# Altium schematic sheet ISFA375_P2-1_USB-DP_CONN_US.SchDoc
size 431 x 279 mm; Date: Not shown in title block; ApprovedBy: Not shown in title block; CheckedBy: Not shown in title block; Author: Not shown in title block; CompanyName: Not shown in title block; DrawnBy: Thomas Mauer; Engineer: Not shown in title block; Organization: Not shown in title block; Address1: Not shown in title block; Address2: Not shown in title block; Address3: Not shown in title block; Address4: Not shown in title block; DocumentNumber: 11; Revision: Use project parameter SCH_Rev; SheetNumber: 11; SheetTotal: 11; PageSetup: Record=PageOptions¦CenterHorizontal=True¦CenterVertical=True¦PrintScale=1.00¦XCorrection=1.00¦YCorrection=1.00¦PrintKind=0¦BorderSize=5000000¦LeftOffset=0¦BottomOffset=0¦Orientation=2¦PaperLength=1000¦PaperWidth=1000¦Scale=100¦PaperSource=15¦PrintQuality=600¦MediaType=1¦DitherType=10¦PaperKind=Letter¦PrintScaleMode=1
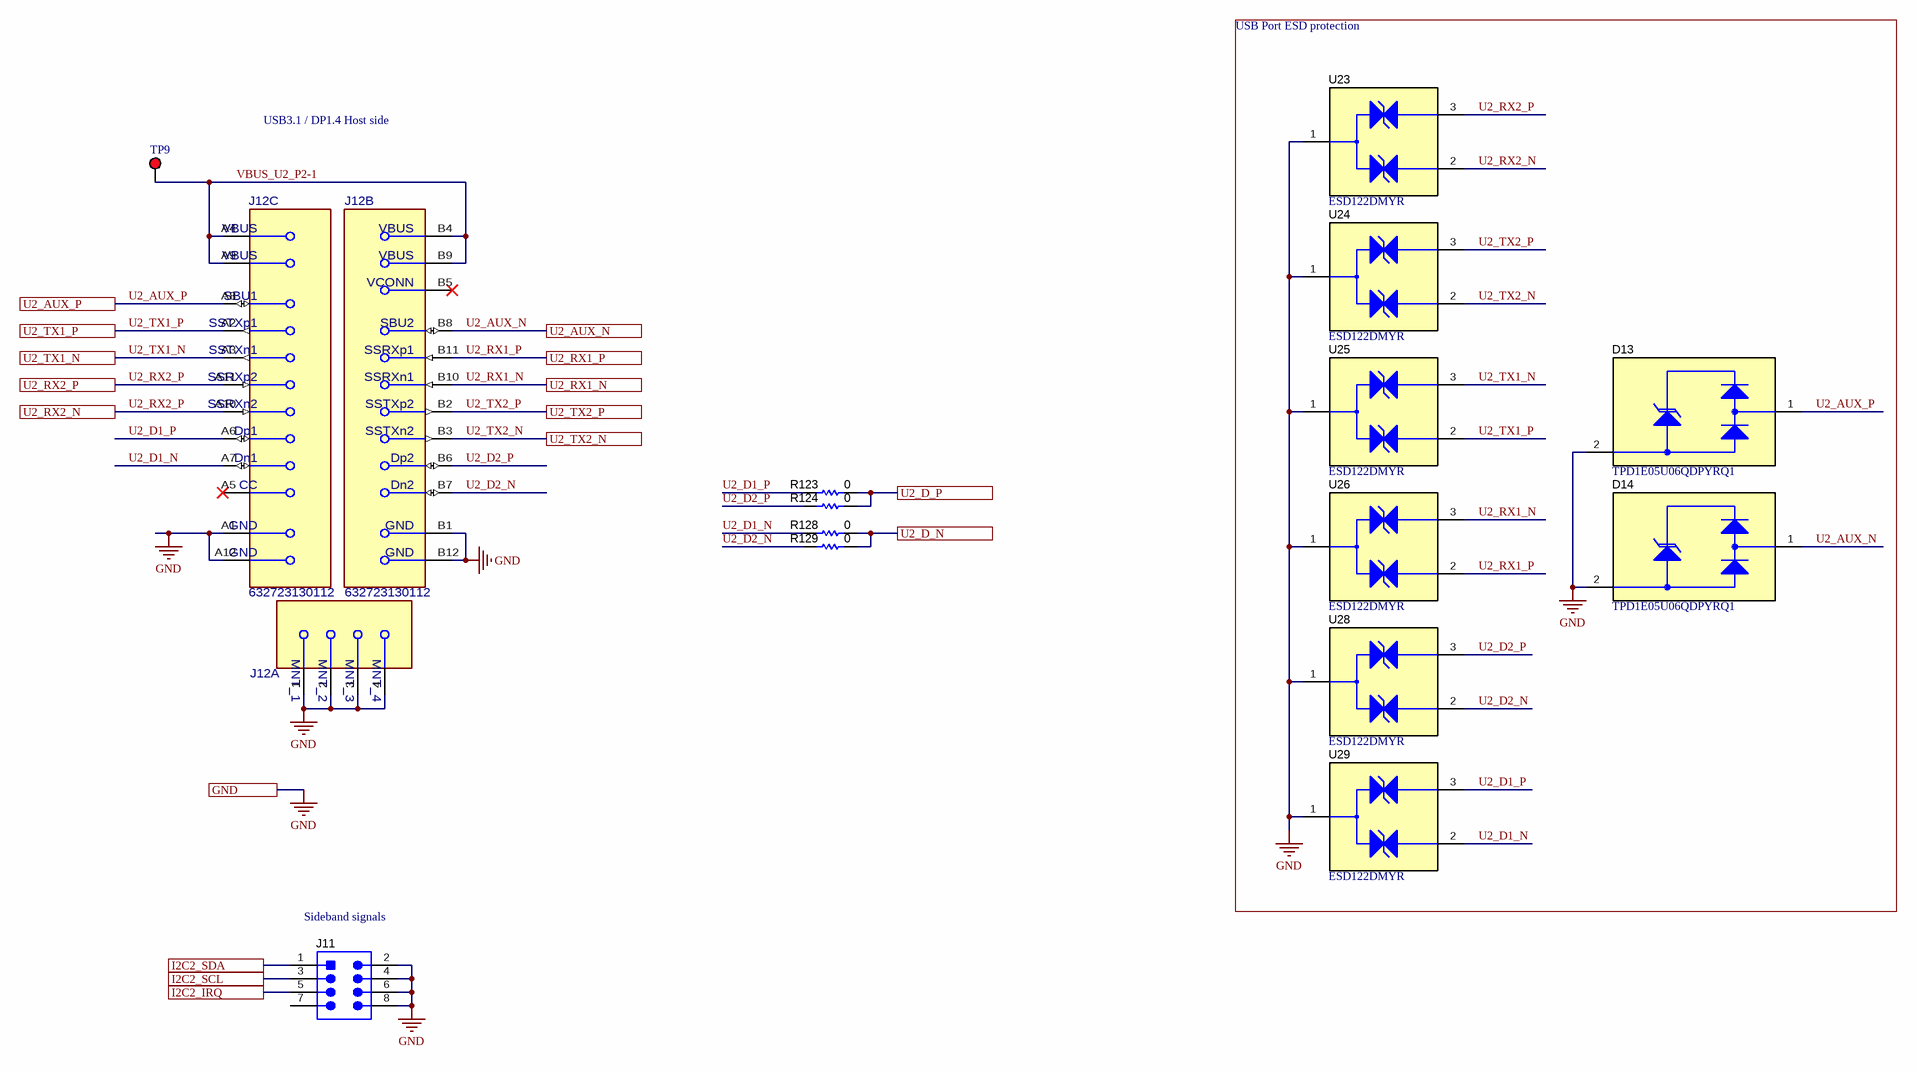
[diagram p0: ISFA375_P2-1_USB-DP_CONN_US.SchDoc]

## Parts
D13  TPD1E05U06QDPYRQ1  [DPY0002A]
D14  TPD1E05U06QDPYRQ1  [DPY0002A]
J11  61000821121  [Wurth_61000821121]  (value not drawn)
J12  632723130112  [FP-632723130112_CONN_USB_9MM65_10MM0-MFG]  (value not drawn)  (parts A,B,C of 3)
R123  ValueDisplayed: 0  [0201]  (hidden comment: CRCW02010000Z0ED)
R124  ValueDisplayed: 0  [0201]  (hidden comment: CRCW02010000Z0ED)
R128  ValueDisplayed: 0  [0201]  (hidden comment: CRCW02010000Z0ED)
R129  ValueDisplayed: 0  [0201]  (hidden comment: CRCW02010000Z0ED)
TP9  5005  [Keystone5005]  (value not drawn)
U23  ESD122DMYR  [DMY0003A]
U24  ESD122DMYR  [DMY0003A]
U25  ESD122DMYR  [DMY0003A]
U26  ESD122DMYR  [DMY0003A]
U28  ESD122DMYR  [DMY0003A]
U29  ESD122DMYR  [DMY0003A]

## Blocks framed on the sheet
USB Port ESD protection: D13 D14 U23-U26 U28 U29

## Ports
GND, I2C2_IRQ, I2C2_SCL, I2C2_SDA, U2_AUX_N, U2_AUX_P, U2_D_N, U2_D_P, U2_RX1_N, U2_RX1_P, U2_RX2_N, U2_RX2_P, U2_TX1_N, U2_TX1_P, U2_TX2_N, U2_TX2_P

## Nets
GND: D13.2(GND) D14.2(GND) J11.2 J11.4 J11.6 J11.8 J12.1(MNT_1) J12.2(MNT_2) J12.3(MNT_3) J12.4(MNT_4) J12.A1(GND) J12.A12(GND) J12.B1(GND) J12.B12(GND) U23.1(GND) U24.1(GND) U25.1(GND) U26.1(GND) U28.1(GND) U29.1(GND) ; port GND
I2C2_IRQ: J11.5 ; port I2C2_IRQ
I2C2_SCL: J11.3 ; port I2C2_SCL
I2C2_SDA: J11.1 ; port I2C2_SDA
U2_AUX_N: D14.1(I/O) J12.B8(SBU2) ; port U2_AUX_N
U2_AUX_P: D13.1(I/O) J12.A8(SBU1) ; port U2_AUX_P
U2_D1_N: J12.A7(Dn1) R128.1 U29.2(IO2)
U2_D1_P: J12.A6(Dp1) R123.1 U29.3(IO1)
U2_D2_N: J12.B7(Dn2) R129.1 U28.2(IO2)
U2_D2_P: J12.B6(Dp2) R124.1 U28.3(IO1)
U2_D_N: R128.2 R129.2 ; port U2_D_N
U2_D_P: R123.2 R124.2 ; port U2_D_P
U2_RX1_N: J12.B10(SSRXn1) U26.3(IO1) ; port U2_RX1_N
U2_RX1_P: J12.B11(SSRXp1) U26.2(IO2) ; port U2_RX1_P
U2_RX2_N: U23.2(IO2)
U2_RX2_P: J12.A10(SSRXn2) J12.A11(SSRXp2) U23.3(IO1) ; port U2_RX2_P, port U2_RX2_N
U2_TX1_N: J12.A3(SSTXn1) U25.3(IO1) ; port U2_TX1_N
U2_TX1_P: J12.A2(SSTXp1) U25.2(IO2) ; port U2_TX1_P
U2_TX2_N: J12.B3(SSTXn2) U24.2(IO2) ; port U2_TX2_N
U2_TX2_P: J12.B2(SSTXp2) U24.3(IO1) ; port U2_TX2_P
VBUS_U2_P2-1: J12.A4(VBUS) J12.A9(VBUS) J12.B4(VBUS) J12.B9(VBUS) TP9.1

Not connected (* = marked no-connect by the designer): J11 7; J12 A5(CC)* B5(VCONN)*

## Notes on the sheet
- USB3.1 / DP1.4 Host side
- (near J11) Sideband signals

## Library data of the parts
D13 D14 = CMP-0073591-4: Automotive 1-Channel Ultra-Low-Capacitance IEC ESD Protection Diode, DPY0002A (X1SON-2); Alternate Manufacturer: Texas Instruments; Alternate PartNumber: TPD1E05U06QDPYTQ1; SizeZ_mm: 0.45; SizeAreaWB_mm2: 3.2; SizeArea_mm2: 0.6; CompType: IC; AEC Category: Q200; AEC Qualified: Y; SizeX_mm: 1.0
J11 = CMP-0079535-2: Header, 2.54mm, 4x2, Gold, SMT; Manufacturer: Wurth Elektronik; Pitch_mm: 2.54; Gender: Male; Cert_UL: Y; Current_A: 3A; Voltage_V: 250V; Shrouded: N; Row_Count: 2
J12 = CMP-0093331-1: USB-C (USB TYPE-C) USB 3.2 Gen 2 (USB 3.1 Gen 2, Superspeed + (USB 3.1)) Receptacle Connector 24 Position Board Edge, Cutout; Surface Mount; Through Hole, Right Angle; Manufacturer: Wurth Electronics; SizeZ_mm: 3.52mm; AEC Qualified: No; Is Female: yes; Usb Standard: USB 3.1; Voltage_V: 20V; Shrouded: true; ContactFinish: Gold,Nickel; Current_A: 5A; Conn Orientation: Horizontal
R123 R124 R128 R129 = CMP-0027008-4: RES, 0, 5%, 0.05 W, 0201; Manufacturer: Vishay-Dale; Power_W: 50mW; TempCo: ppm/C; Value_Code: 0000; Value: 0; EIA_Code: E24; SizeX_mm: 0.6; SizeY_mm: 0.3; SizeZ_mm: 0.26; Value2: 0.05W; SizeArea_mm2: 0.18; AEC Qualified: N; AEC Category: Q200
TP9 = CMP-0055142-1: Test Point, Compact, Red, TH; Manufacturer: Keystone; CNHeader: FALSE; Green_Lifecycle: Active; Green_REACh: Passed; ContactFinish: Silver; CT: TRUE
U23-U26 U28 U29 = CMP-0013358-2: 2-Channel ESD Protection Diode for USB Type-C and HDMI 2.0, DMY0003A (X1SON-3); Manufacturer: Texas Instruments; SizeX_mm: 0.6; SizeY_mm: 1.3; CompType: IC; SizeZ_mm: 0.4; SizeArea_mm2: 0.78; SizeAreaWB_mm2: 3.68; U/M: EA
